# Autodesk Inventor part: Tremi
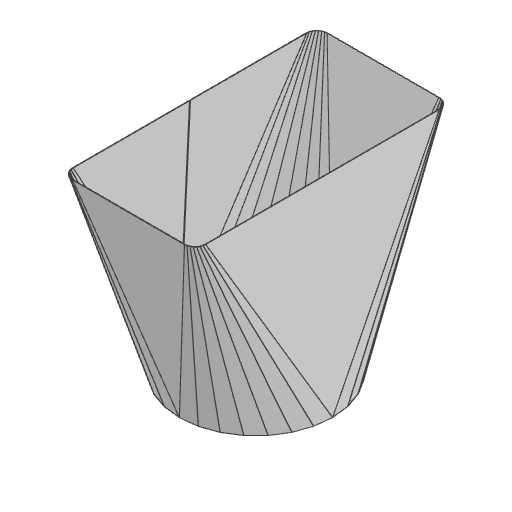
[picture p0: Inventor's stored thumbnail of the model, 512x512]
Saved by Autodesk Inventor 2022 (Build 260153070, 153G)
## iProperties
Created: 2021-07
Part Number: Tremi
Material: Générique
Document SubType Name: Sheet Metal
Designer: Fabian
Density: 1 g/cm^3
Flat Pattern Width: 27.4069 cm
Flat Pattern Length: 67.8626 cm
Flat Pattern Area: 1859.9 cm^2
Sheet Metal Rule: Par défaut_mm
Sheet Metal Width: 274,069 mm
Sheet Metal Length: 678,626 mm
Sheet Metal Area: 185990,285 mm^2
Appearance: Par défaut
Author: Fabian
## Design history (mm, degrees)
derived "Tremie.ipt"
feature "Tremi::Tremie.ipt" dims "d0" = 10
tag "FonctionRepérage1"
node "Solide1"
feature "Définition1"
other parameters: "Epaisseur" = 0.5 (derived), "RayonPli" = 0.5 (= Epaisseur), "LargeurGrugeage" = 0.5 (= Epaisseur), "ProfondeurGrugeage" = 0.25 (= 0.5 x Epaisseur), "TailleGrugeage" = 2 (= 4 x Epaisseur), "SeamGap" = 0.01, "RestesMinimum" = 1 (= 2 x Epaisseur), "Rayondetransition" = 0.5 (= RayonPli), "TailleRayonJacobi" = 0.5 (= RayonPli), "TailleJeu" = 0.5 (= Epaisseur), "d1" = 0.5 (= Epaisseur), "Epaisseur" = 0.5, "LargeurGrugeage" = 0.5, "ProfondeurGrugeage" = 0.25, "RayonPli" = 0.5, "Rayondetransition" = 0.5, "RestesMinimum" = 1, "TailleGrugeage" = 2, "TailleJeu" = 0.5, "TailleRayonJacobi" = 0.5
